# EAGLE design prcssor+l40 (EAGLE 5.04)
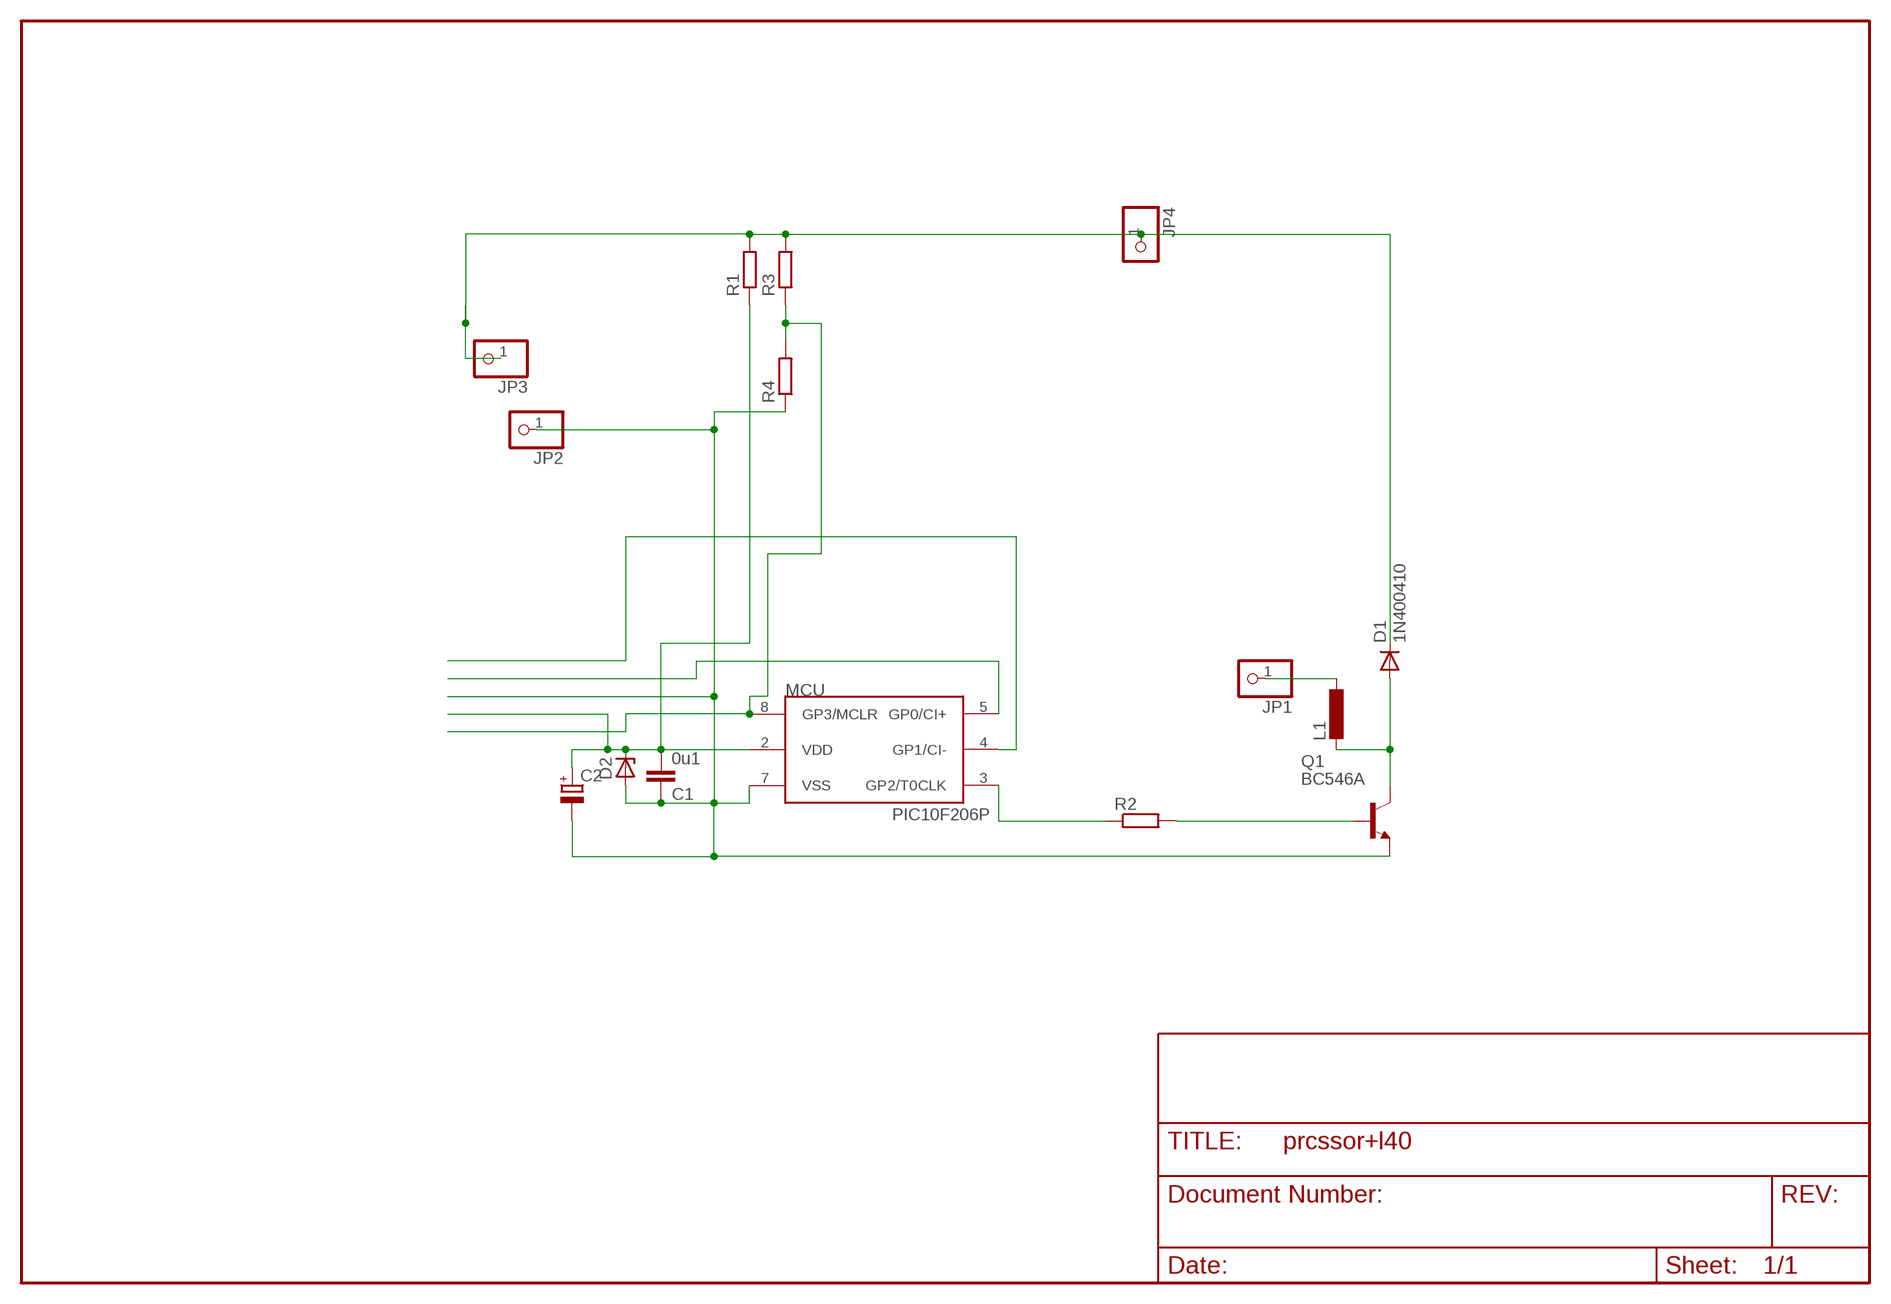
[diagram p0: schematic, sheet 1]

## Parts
C1  0u1  C-EUC1210  [C1210]
C2  CPOL-EUE2.5-5  [E2,5-5]
D1  1N400410  [DO41-10]
D2  ZENER-DIODEZD-10  [ZDIO-10]
JP1  PINHD-1X1  [1X01]
JP2  PINHD-1X1  [1X01]
JP3  PINHD-1X1  [1X01]
JP4  PINHD-1X1  [1X01]
L1  L-EU0207/7  [0207/7]
MCU  PIC10F206P  [DIL8]
Q1  BC546A  [TO92-EBC]
R1  R-EU_0207/10  [0207/10]
R2  R-EU_0204/7  [0204/7]
R3  R-EU_0207/10  [0207/10]
R4  R-EU_0207/10  [0207/10]

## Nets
GP0: MCU.5(GP0/CI+)
GP1: MCU.4(GP1/CI-)
GP2: MCU.3(GP2/T0CLK) R2.1
GP3: MCU.8(GP3/MCLR) R3.1 R4.2
HOTSPOT: D1.A L1.2 Q1.C
LED-: JP1.1 L1.1
N$1: Q1.B R2.2
V+: D1.C JP3.1 JP4.1 R1.2 R3.2
VDD1: C1.2 C2.+ D2.C MCU.2(VDD) R1.1
VSS-V-: C1.1 C2.- D2.A JP2.1 MCU.7(VSS) Q1.E R4.1

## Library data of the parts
C1 = rcl:C-EU: CAPACITOR, European symbol
C2 = rcl:CPOL-EU: POLARIZED CAPACITOR, European symbol
D1 = diode-1:1N4004: DIODE
D2 = diode-1:ZENER-DIODE: Z-Diode
JP1-JP4 = pinhead(2):PINHD-1X1: PIN HEADER
L1 = rcl:L-EU: INDUCTOR, European symbol
MCU = microchip-3:PIC10F2*: uPC nW 0,25/0,5k Program Flash memory Comparator
Q1 = transistor-npn:BC546*: NPN Transistor
R1-R4 = rcl:R-EU_: RESISTOR, European symbol

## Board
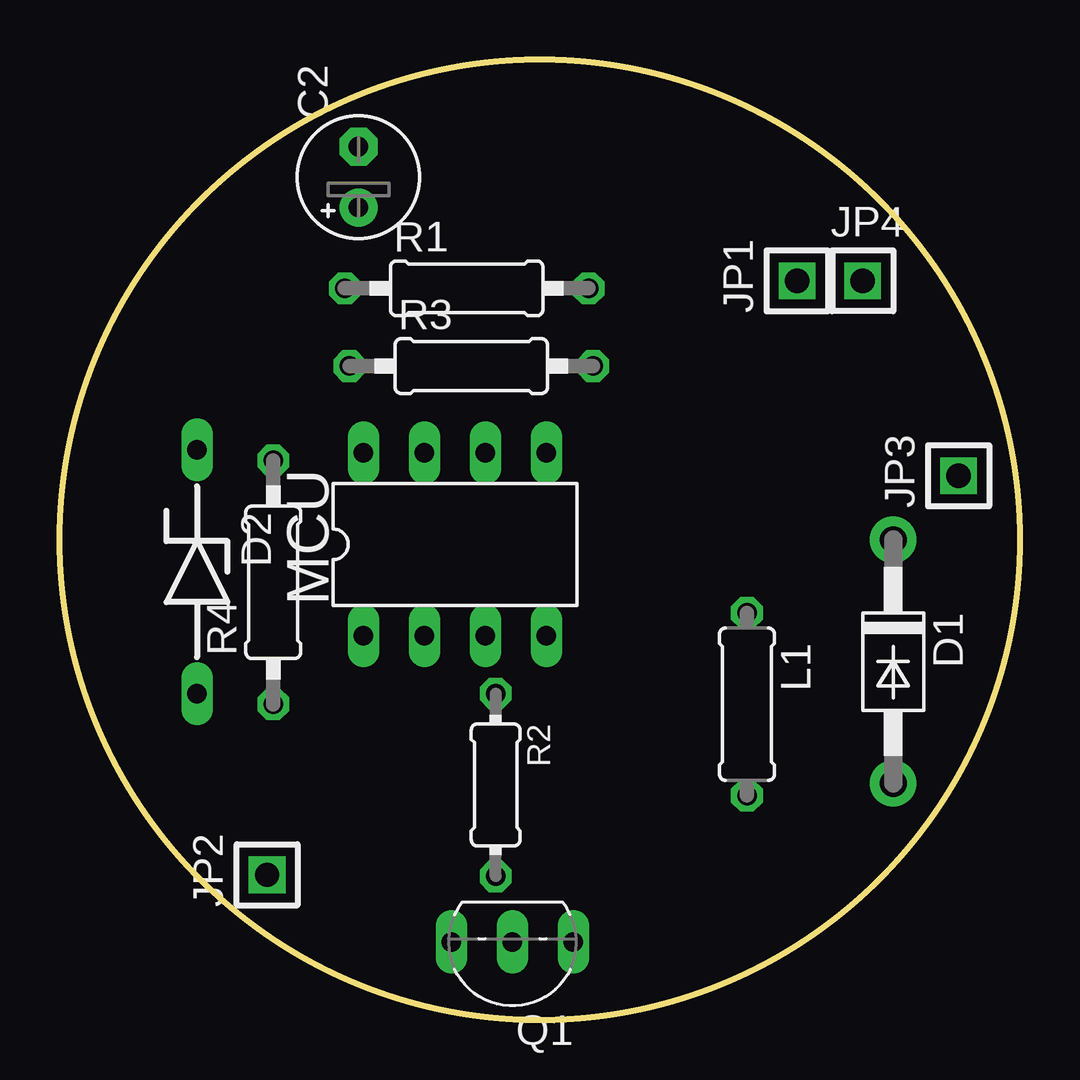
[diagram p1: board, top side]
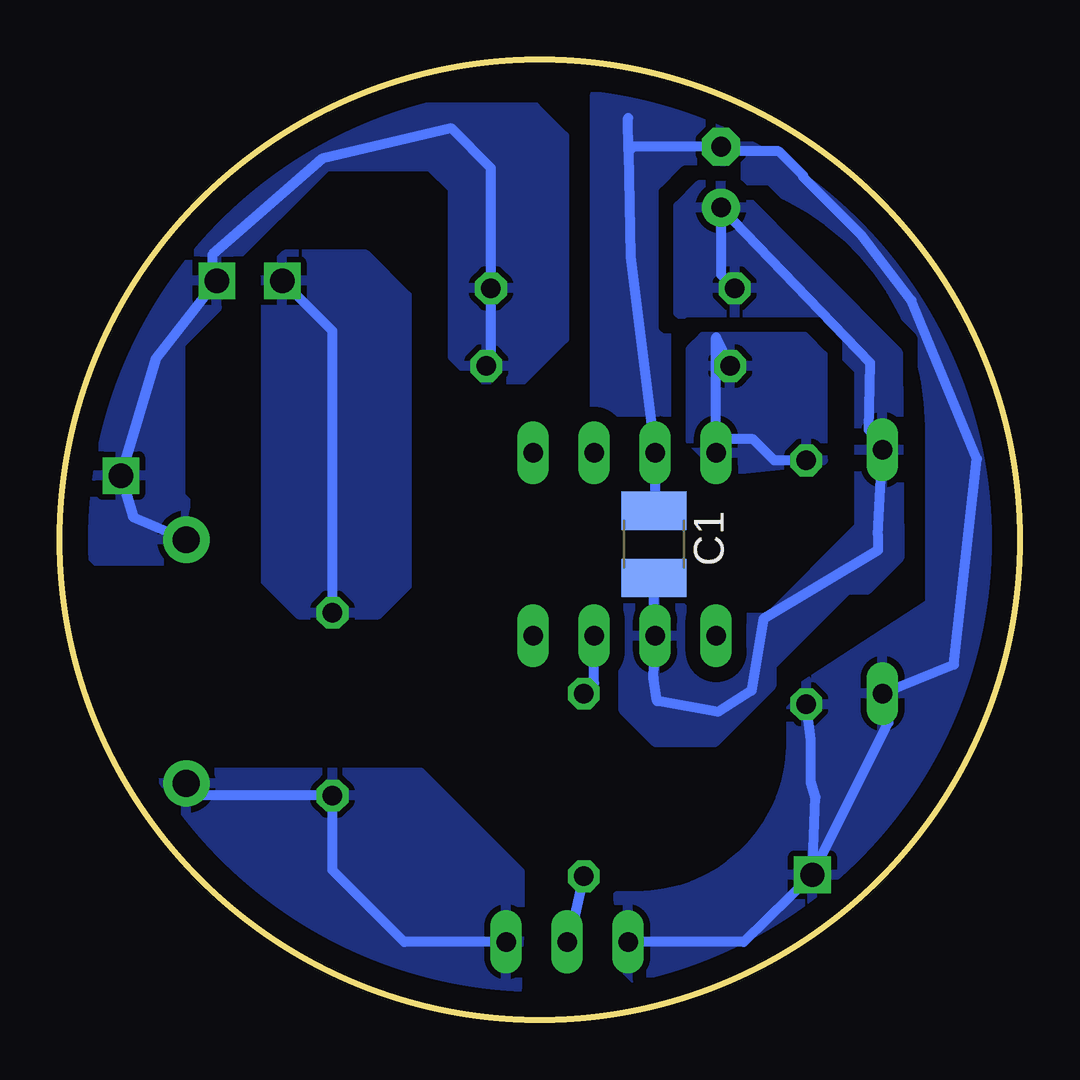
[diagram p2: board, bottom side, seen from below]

Size 40 x 40 mm. Coordinates in mm from the lower left corner, seen from the top.
Outline: circle at 20,20 radius 20
Copper layers (1*16): Top 0.035mm / dielectric 1.5mm / Bottom 0.035mm
Design rules "default": minimum track width 10mil, minimum drill 24mil, track to track 8mil, track to pad 8mil, pad to pad 8mil, via to via 8mil, smd to smd 8mil, copper to edge 40mil, drill to drill 8mil, minimum pad ring 10mil, minimum via ring 8mil, stop-mask expansion 4mil, vias tented up to drill 0mil, thermal gap 10mil

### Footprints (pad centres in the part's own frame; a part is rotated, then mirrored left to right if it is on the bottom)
C1210 = smd 1.6 x 2.7: 1 -1.4,0; 2 1.4,0
E2,5-5 = drill 0.813 pad 1.6 round: + -1.27,0 | drill 0.813 pad 1.6 octagon: - 1.27,0
DO41-10 = drill 1.118 pad 1.93 round: A 5.08,0; C -5.08,0
ZDIO-10 = drill 0.813 long: A 5.08,0; C -5.08,0
1X01 = drill 1.016 square: 1 0,0
0207/7 = drill 0.813 octagon: 1 -3.81,0; 2 3.81,0
DIL8 = drill 0.813 long: 1 -3.81,-3.81; 2 -1.27,-3.81; 3 1.27,-3.81; 4 3.81,-3.81; 5 3.81,3.81; 6 1.27,3.81; 7 -1.27,3.81; 8 -3.81,3.81
TO92-EBC = drill 0.813 long: B 0,-1.27; C -2.54,-1.27; E 2.54,-1.27
0207/10 = drill 0.813 octagon: 1 -5.08,0; 2 5.08,0
0204/7 = drill 0.813 octagon: 1 -3.81,0; 2 3.81,0

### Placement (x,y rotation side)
C1  15.24,19.81 270 bottom
C2  12.45,35.12 90 top
D1  34.73,14.92 270 top
D2  5.71,18.67 270 top
JP1  30.73,30.8 90 top
JP2  8.64,6.03 90 top
JP3  37.47,22.67 90 top
JP4  33.46,30.8 0 top
L1  28.64,13.14 270 top
MCU  16.46,19.81 0 top
Q1  18.86,1.97 180 top
R1  16.95,30.48 0 top
R2  18.16,9.78 270 top
R3  17.14,27.24 0 top
R4  8.89,18.22 90 top

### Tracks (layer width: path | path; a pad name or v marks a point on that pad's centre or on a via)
GP2
  Bottom 0.406: MCU.3 17.73,14.02 R2.1
GP3
  Bottom 0.406: R4.2 10.22,23.3 11.11,24.19 12.08,24.19 MCU.8 12.65,28.43 R3.1
  pour Bottom (isolate 0.406): 8.19,23.3 8.19,27.69 8.95,28.45 13.21,28.45 13.72,27.94 13.72,24.13 12.45,22.86
HOTSPOT
  Bottom 0.406: Q1.C 25.65,3.24 28.64,6.22 L1.2 34.23,9.34 D1.A
  pour Bottom (isolate 0.406, rank 3): 20.83,4.06 20.83,6.16 24.96,10.29 35.5,10.29 35.69,10.1 35.69,8.7 31.05,4.06 31.05,3.62 29.46,2.03 26.29,2.03 25.02,0.76 21.21,0.76 20.95,1.02
LED-
  Bottom 0.406: L1.1 28.64,28.7 JP1.1
  pour Bottom (isolate 0.406, rank 2): 31.43,28.32 31.43,18.29 30.04,16.89 26.73,16.89 25.53,18.1 25.53,30.16 27.24,31.88 30.61,31.88 31.43,31.05
N$1
  Bottom 0.406: R2.2 18.73,3.37 Q1.B
V+
  Bottom 0.406: D1.C 36.96,20.95 JP3.1 36.01,27.56 JP4.1 33.66,30.99 33.66,31.88 29.08,35.88 23.69,37.15 22.04,35.5 R1.2 22.04,27.43 R3.2
  pour Bottom (isolate 0.406, rank 3): 35.31,19.11 38.48,19.11 39.5,20.13 39.5,25.02 37.78,26.73 37.78,29.21 33.34,33.66 33.27,33.66 28.89,38.04 20.19,38.04 18.99,36.83 18.99,28.38 20.7,26.67 22.67,26.67 23.62,27.62 23.62,34.61 24.57,35.56 28.89,35.56 33.08,31.37 33.08,30.04 34.99,28.13 34.99,21.84 34.73,21.59
VDD1
  Bottom 0.406: R1.1 12.45,31.05 C2.+ 6.22,27.37 6.29,24.57 5.71,24.19 D2.C 5.91,20.19 5.91,19.56 10.67,16.7 11.18,13.72 12.57,12.83 15.11,13.27 15.26,14.24 MCU.2 15.24,16.05 C1.2
  pour Bottom (isolate 0.61, rank 2): 8.57,28.96 13.72,28.96 14.22,29.46 14.22,33.91 13.34,34.8 12,34.8 5.08,27.81 5.02,19.24 6.35,17.91 7.18,17.91 10.35,14.73 10.35,13.91 12.7,11.56 15.18,11.56 16.51,12.89 16.51,17.53 16.26,17.78 14.67,17.78 13.65,16.76 10.48,16.76 6.67,20.57 6.67,27.05
VSS-V-
  Bottom 0.406: Q1.E 11.49,3.24 JP2.1 | JP2.1 8.51,9.27 8.7,9.91 8.7,11.68 R4.1 | JP2.1 5.46,12.38 D2.A 2.73,14.8 1.78,23.37 4.51,29.97 6.6,32.7 9.02,35.12 9.02,35.18 10.03,36.2 12.26,36.2 C2.- 16.09,36.39 16.29,36.19 | 16.29,36.19 16.21,31.8 MCU.7 15.19,21.25 C1.1 | 16.29,36.19 16.32,37.59
  pour Bottom (isolate 0.61, rank 4): 16.57,4.13 16.57,2.22 15.56,1.21 11.11,2.22 6.54,5.84 5.97,5.84 4.45,8.76 arc-90 1.4,22.99 0.76,24.32 arc-90 15.81,38.73 17.4,38.73 arc-90 17.72,38.42 17.72,25.53 arc-90 17.53,25.34 14.61,25.34 arc-90 14.41,25.53 14.41,35.43 arc90 3.75,24.77 3.75,17.34 9.59,13.53 9.53,13.53 9.53,11.56 arc90 15.94,5.14 16.76,5.14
